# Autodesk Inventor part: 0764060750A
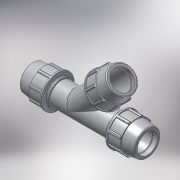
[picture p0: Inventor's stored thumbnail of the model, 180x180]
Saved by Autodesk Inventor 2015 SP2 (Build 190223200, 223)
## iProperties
Created: 2017-02
Part Number: 0764060750A
Material: PVC-Piping
Description: PLASSON 45° TEE 75-75-75
Document SubType Name: Modeling
Designer: KIM
Mass: 92.6774 g
Surface Area: 199.44 cm^2
Volume: 66.1981 cm^3
Density: 1.4 g/cm^3
Appearance: Smooth - White
Author: KIM
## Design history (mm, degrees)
derived "87640.ipt"
feature "Solid1::87640.ipt"
feature "Solid3::87640.ipt"
tag "TaggingFeature1"
body "Solid1"
other parameters: "d2" = 75, "d4" = 18.125, "d5" = 43.5, "d7" = 132, "d11" = 7.25, "d13" = 120 deg, "d14" = 97.5, "d15" = 8 deg, "d16" = 105.6, "d18" = 3.75, "d19" = 35 deg, "d20" = 17.5 deg, "d21" = 122.76, "d23" = 0, "d25" = 360 deg, "d27" = 2.64, "d33" = 1.5, "d42" = 52.2, "d43" = 3.96, "d46" = 2.25, "d68" = 6.525, "d91" = 92.4, "d93" = 132, "d95" = 67.5, "d134" = 217.5, "d138" = 45 deg, "d141" = 204, "d144" = 0, "d146" = 0, "d150" = 3.75, "d158" = 1.5, "d159" = 5.28, "d160" = 0, "d165" = 250.8, "d166" = 122.76, "d167" = 35 deg, "d168" = 17.5 deg, "d170" = 0, "d172" = 360 deg, "d174" = 3.96, "d177" = 2.64, "d180" = 5.28, "d181" = 0, "d_" = 75, "E_" = 132, "A_" = 204, "l_" = 132, "H_" = 435
